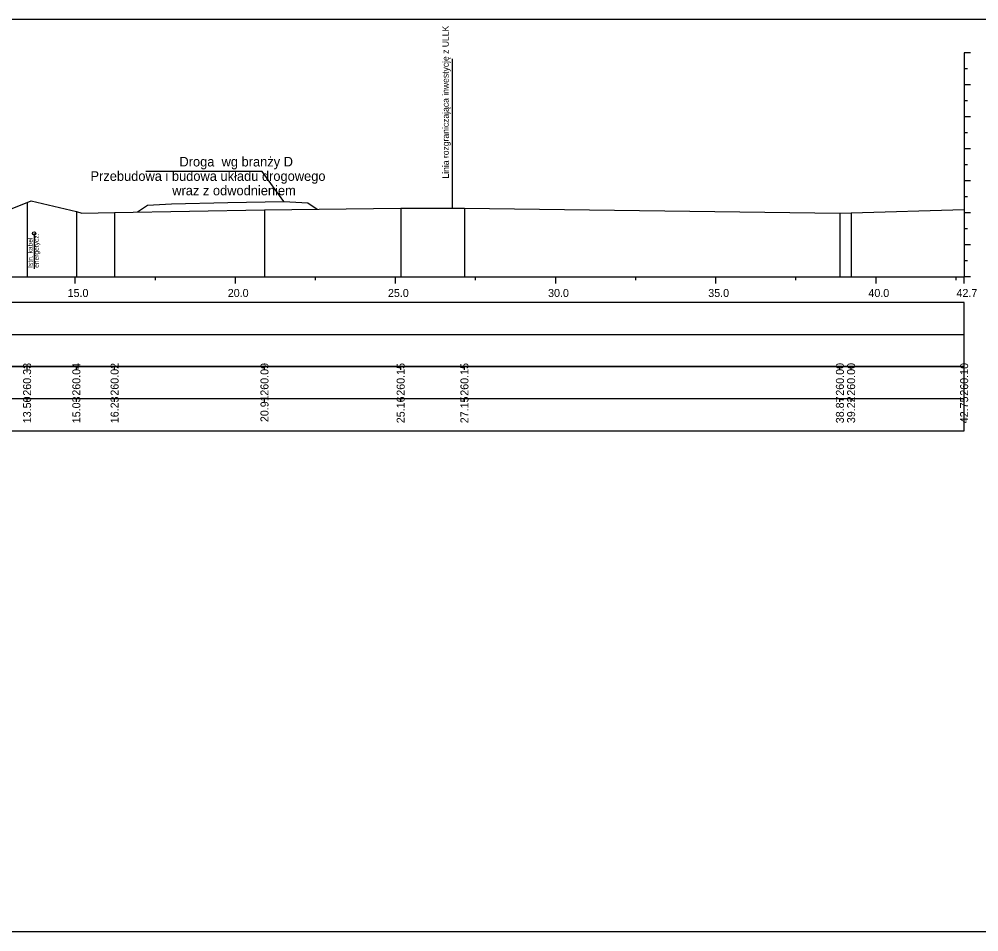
# Model space of a CAD drawing. Extents: x 6516023 to 6560129, y 5513077 to 5529206.
# Drawn here: x 6517781.46 to 6517811.42, y 5514451.16 to 5514479.66 of the extents above; entities that cross this region are included whole.
import ezdxf

# ---------------------------------------------------------------- set-up
doc = ezdxf.new("R2010")
doc.units = 0
for name, color, linetype in [('TOR_PRZEK_P-inne branze', 7, 'Continuous'), ('TOR_PRZEK_P-kable', 7, 'Continuous'), ('TOR_PRZEK_P-tabelka istniejace', 7, 'Continuous'), ('TOR_PRZEK_P-tabelka projektowane', 7, 'Continuous'), ('TOR_PRZEK_P-teren istniejacy', 7, 'Continuous'), ('TOR_PRZEK_P-uklad odniesienia', 7, 'Continuous'), ('TOR_PS_T-granica PKP-projektowana', 7, 'Continuous'), ('TOR_RAMKI-ramka+tabelka 1', 7, 'Continuous')]:
    doc.layers.add(name, color=color, linetype=linetype)

msp = doc.modelspace()

# ---------------------------------------------------------------- linework, layer by layer
at = {"layer": 'TOR_PRZEK_P-inne branze'}
for p, q in [((6517789.045, 5514474.897), (6517785.421, 5514474.897)), ((6517789.721, 5514473.962), (6517789.045, 5514474.897))]:
    msp.add_line(p, q, dxfattribs=at)
msp.add_lwpolyline([(6517785.153, 5514473.635), (6517785.471, 5514473.847), (6517786.221, 5514473.892), (6517787.971, 5514473.927), (6517789.721, 5514473.962), (6517790.471, 5514473.917), (6517790.764, 5514473.722)], dxfattribs=at)
at = {"layer": 'TOR_PRZEK_P-kable'}
msp.add_line((6517781.927, 5514472.966), (6517781.927, 5514471.856), dxfattribs=at)
msp.add_circle((6517781.927, 5514472.966), 0.05, dxfattribs=at)
at = {"layer": 'TOR_PRZEK_P-tabelka istniejace'}
for p, q in [((6517781.709, 5514468.706), (6517781.709, 5514468.806)), ((6517783.247, 5514468.706), (6517783.247, 5514468.806)), ((6517784.441, 5514468.706), (6517784.441, 5514468.806)), ((6517789.12, 5514468.706), (6517789.12, 5514468.806)), ((6517793.372, 5514468.706), (6517793.372, 5514468.806)), ((6517795.363, 5514468.706), (6517795.363, 5514468.806)), ((6517807.084, 5514468.706), (6517807.084, 5514468.806)), ((6517807.434, 5514468.706), (6517807.434, 5514468.806)), ((6517810.963, 5514468.706), (6517810.963, 5514468.806)), ((6517727.163, 5514467.806), (6517810.963, 5514467.806)), ((6517781.709, 5514467.706), (6517781.709, 5514467.806)), ((6517783.247, 5514467.706), (6517783.247, 5514467.806)), ((6517784.441, 5514467.706), (6517784.441, 5514467.806)), ((6517789.12, 5514467.706), (6517789.12, 5514467.806)), ((6517793.372, 5514467.706), (6517793.372, 5514467.806)), ((6517795.363, 5514467.706), (6517795.363, 5514467.806)), ((6517807.084, 5514467.706), (6517807.084, 5514467.806)), ((6517807.434, 5514467.706), (6517807.434, 5514467.806)), ((6517810.963, 5514467.706), (6517810.963, 5514467.806))]:
    msp.add_line(p, q, dxfattribs=at)
for points in [[(6517781.709, 5514473.936), (6517781.709, 5514471.806), (6517781.709, 5514471.676), (6517781.709, 5514471.606)], [(6517793.372, 5514473.757), (6517793.372, 5514471.806), (6517793.372, 5514471.676), (6517793.372, 5514471.606)], [(6517795.363, 5514473.757), (6517795.363, 5514471.806), (6517795.363, 5514471.676), (6517795.363, 5514471.606)], [(6517783.247, 5514473.65), (6517783.247, 5514471.806), (6517783.247, 5514471.676), (6517783.247, 5514471.606)], [(6517784.441, 5514473.623), (6517784.441, 5514471.806), (6517784.441, 5514471.676), (6517784.441, 5514471.606)], [(6517789.12, 5514473.7), (6517789.12, 5514471.806), (6517789.12, 5514471.676), (6517789.12, 5514471.606)], [(6517807.084, 5514473.603), (6517807.084, 5514471.806), (6517807.084, 5514471.676), (6517807.084, 5514471.606)], [(6517807.434, 5514473.606), (6517807.434, 5514471.806), (6517807.434, 5514471.676), (6517807.434, 5514471.606)], [(6517810.963, 5514473.71), (6517810.963, 5514471.806), (6517810.963, 5514471.676), (6517810.963, 5514471.606)]]:
    msp.add_lwpolyline(points, dxfattribs=at)
msp.add_lwpolyline([(6517727.163, 5514468.806), (6517727.163, 5514466.806), (6517810.963, 5514466.806), (6517810.963, 5514468.806)], close=True, dxfattribs=at)
at = {"layer": 'TOR_PRZEK_P-tabelka projektowane'}
msp.add_line((6517727.163, 5514469.806), (6517810.963, 5514469.806), dxfattribs=at)
msp.add_lwpolyline([(6517727.163, 5514470.806), (6517727.163, 5514468.806), (6517810.963, 5514468.806), (6517810.963, 5514470.806)], close=True, dxfattribs=at)
at = {"layer": 'TOR_PRZEK_P-teren istniejacy'}
msp.add_lwpolyline([(6517780.491, 5514473.451), (6517781.709, 5514473.936), (6517781.837, 5514473.987), (6517783.247, 5514473.65), (6517783.419, 5514473.602), (6517784.441, 5514473.623), (6517789.12, 5514473.7), (6517793.372, 5514473.757), (6517795.363, 5514473.757), (6517807.084, 5514473.603), (6517807.434, 5514473.606), (6517810.963, 5514473.71)], dxfattribs=at)
at = {"layer": 'TOR_PRZEK_P-uklad odniesienia'}
for p, q in [((6517810.963, 5514478.606), (6517810.963, 5514471.606)), ((6517811.163, 5514478.606), (6517810.963, 5514478.606)), ((6517811.063, 5514478.106), (6517810.963, 5514478.106)), ((6517811.163, 5514477.606), (6517810.963, 5514477.606)), ((6517811.063, 5514477.106), (6517810.963, 5514477.106)), ((6517811.163, 5514476.606), (6517810.963, 5514476.606)), ((6517811.063, 5514476.106), (6517810.963, 5514476.106)), ((6517811.163, 5514475.606), (6517810.963, 5514475.606)), ((6517811.063, 5514475.106), (6517810.963, 5514475.106)), ((6517811.163, 5514474.606), (6517810.963, 5514474.606)), ((6517811.063, 5514474.106), (6517810.963, 5514474.106)), ((6517811.163, 5514473.606), (6517810.963, 5514473.606)), ((6517811.063, 5514473.106), (6517810.963, 5514473.106)), ((6517811.163, 5514472.606), (6517810.963, 5514472.606)), ((6517811.063, 5514472.106), (6517810.963, 5514472.106)), ((6517730.963, 5514471.606), (6517810.963, 5514471.606)), ((6517783.213, 5514471.406), (6517783.213, 5514471.606)), ((6517785.713, 5514471.506), (6517785.713, 5514471.606)), ((6517788.213, 5514471.406), (6517788.213, 5514471.606)), ((6517790.713, 5514471.506), (6517790.713, 5514471.606)), ((6517793.213, 5514471.406), (6517793.213, 5514471.606)), ((6517795.713, 5514471.506), (6517795.713, 5514471.606)), ((6517798.213, 5514471.406), (6517798.213, 5514471.606)), ((6517800.713, 5514471.506), (6517800.713, 5514471.606)), ((6517803.213, 5514471.406), (6517803.213, 5514471.606)), ((6517805.713, 5514471.506), (6517805.713, 5514471.606)), ((6517808.213, 5514471.406), (6517808.213, 5514471.606)), ((6517810.713, 5514471.506), (6517810.713, 5514471.606)), ((6517810.963, 5514471.406), (6517810.963, 5514471.606)), ((6517811.163, 5514471.606), (6517810.963, 5514471.606))]:
    msp.add_line(p, q, dxfattribs=at)
at = {"layer": 'TOR_PS_T-granica PKP-projektowana'}
msp.add_line((6517794.986, 5514473.757), (6517794.986, 5514478.415), dxfattribs=at)
at = {"layer": 'TOR_RAMKI-ramka+tabelka 1'}
msp.add_lwpolyline([(6517724.513, 5514479.656), (6517972.013, 5514479.656), (6517972.013, 5514451.156), (6517724.513, 5514451.156)], close=True, dxfattribs=at)

# ---------------------------------------------------------------- texts
at = {"layer": 'TOR_PRZEK_P-inne branze'}
for s, p in [('Droga  wg branży D', (6517786.465, 5514475.057)), ('Przebudowa i budowa układu drogowego', (6517783.688, 5514474.607)), ('wraz z odwodnieniem ', (6517786.24, 5514474.157))]:
    msp.add_text(s, height=0.3, dxfattribs=at).set_placement(p)
at = {"layer": 'TOR_PRZEK_P-kable'}
for s, p in [('energetycz.', (6517782.076, 5514471.892)), ('Istn. kabel', (6517781.882, 5514471.892))]:
    msp.add_text(s, height=0.14999, rotation=90.0511, dxfattribs=at).set_placement(p)
at = {"layer": 'TOR_PRZEK_P-tabelka istniejace'}
for s, p in [('260.33', (6517781.834, 5514467.898)), ('260.04', (6517783.372, 5514467.899)), ('260.02', (6517784.566, 5514467.9)), ('260.09', (6517789.245, 5514467.898)), ('260.15', (6517793.497, 5514467.897)), ('260.15', (6517795.488, 5514467.897)), ('260.00', (6517807.209, 5514467.898)), ('260.00', (6517807.559, 5514467.898)), ('260.10', (6517811.088, 5514467.898)), ('13.50', (6517781.834, 5514467.038)), ('15.03', (6517783.372, 5514467.038)), ('16.23', (6517784.566, 5514467.038)), ('20.91', (6517789.245, 5514467.073)), ('25.16', (6517793.497, 5514467.038)), ('27.15', (6517795.488, 5514467.037)), ('38.87', (6517807.209, 5514467.038)), ('39.22', (6517807.559, 5514467.04)), ('42.75', (6517811.088, 5514467.037))]:
    msp.add_text(s, height=0.25, rotation=90, dxfattribs=at).set_placement(p)
at = {"layer": 'TOR_PRZEK_P-uklad odniesienia'}
for s, p in [('15.0', (6517782.974, 5514470.981)), ('20.0', (6517787.974, 5514470.981)), ('25.0', (6517792.974, 5514470.981)), ('30.0', (6517797.974, 5514470.981)), ('35.0', (6517802.974, 5514470.981)), ('40.0', (6517807.974, 5514470.981)), ('42.7', (6517810.724, 5514470.981))]:
    msp.add_text(s, height=0.25, dxfattribs=at).set_placement(p)
at = {"layer": 'TOR_PS_T-granica PKP-projektowana'}
msp.add_text('Linia rozgraniczająca inwestycję z ULLK', height=0.2, rotation=90.0511, dxfattribs=at).set_placement((6517794.876, 5514474.679))

doc.saveas('drawing.dxf')
